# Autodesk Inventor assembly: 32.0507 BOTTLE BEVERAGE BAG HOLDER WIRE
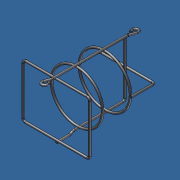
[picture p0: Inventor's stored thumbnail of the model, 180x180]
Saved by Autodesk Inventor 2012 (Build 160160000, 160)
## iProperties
Created: 2013-04
Part Number: 32.0507 BOTTLE BEVERAGE BAG HOLDER WIRE
Document SubType Name: Assembly
Designer: Admin
Author: Admin
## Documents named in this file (9)
- C:\Andys Backup Data\ANDY'S INVENTOR\INVENTOR LIBRARIES\PARTS LIBRARY\WORKSTATION\SUBCOMPONENTS\32.0507 BOTTLE BEVERAGE BAG HOLDER WIRE.iam
- C:\Andys Backup Data\ANDY'S INVENTOR\INVENTOR LIBRARIES\PARTS LIBRARY\WORKSTATION\SUBCOMPONENTS\32.0507-1.ipt
- C:\Andys Backup Data\ANDY'S INVENTOR\INVENTOR LIBRARIES\PARTS LIBRARY\WORKSTATION\SUBCOMPONENTS\32.0507-2.ipt
- C:\Andys Backup Data\ANDY'S INVENTOR\INVENTOR LIBRARIES\PARTS LIBRARY\WORKSTATION\SUBCOMPONENTS\32.0507-3.ipt
- C:\Andys Backup Data\ANDY'S INVENTOR\INVENTOR LIBRARIES\PARTS LIBRARY\WORKSTATION\SUBCOMPONENTS\32.0507-4.ipt
- C:\Andys Backup Data\ANDY'S INVENTOR\INVENTOR LIBRARIES\PARTS LIBRARY\WORKSTATION\SUBCOMPONENTS\32.0507-5.ipt
- C:\Andys Backup Data\ANDY'S INVENTOR\INVENTOR LIBRARIES\PARTS LIBRARY\WORKSTATION\SUBCOMPONENTS\32.0507-6.ipt
- C:\Andys Backup Data\ANDY'S INVENTOR\INVENTOR LIBRARIES\PARTS LIBRARY\WORKSTATION\SUBCOMPONENTS\32.0507-7.ipt
- C:\Andys Backup Data\ANDY'S INVENTOR\INVENTOR LIBRARIES\PARTS LIBRARY\WORKSTATION\SUBCOMPONENTS\32.0507-8.ipt
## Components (8 placed, 8 different names)
1. 32.0507-1:1
2. 32.0507-2:1
3. 32.0507-3:1
4. 32.0507-4:1
5. 32.0507-5:1
6. 32.0507-6:1
7. 32.0507-7:1
8. 32.0507-8:1
